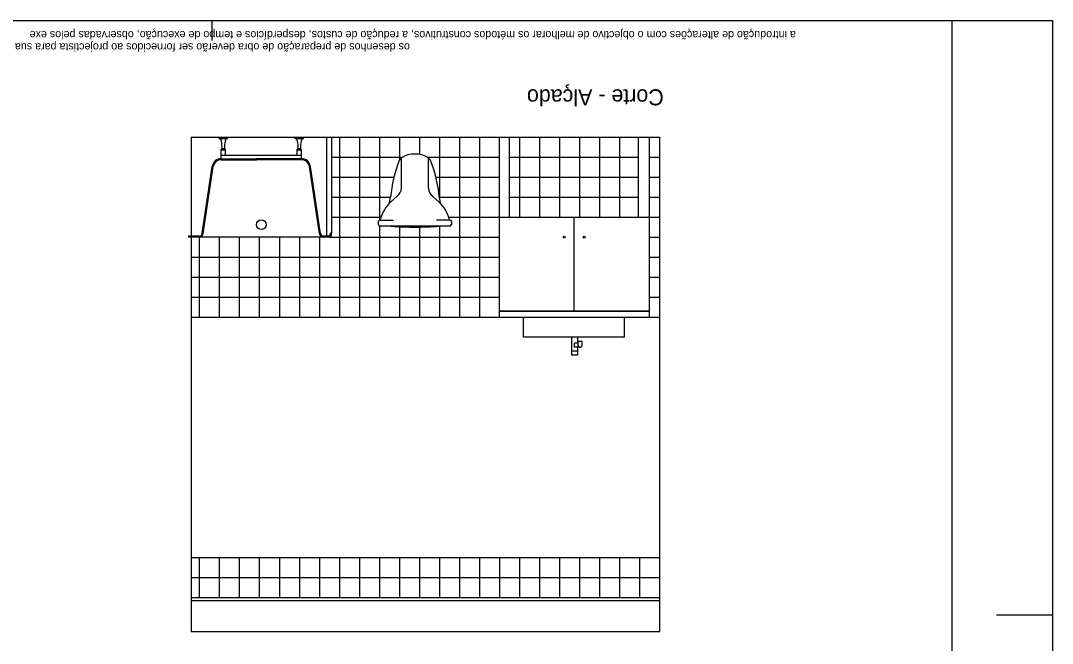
# Model space of a CAD drawing. Extents: x 1289.5 to 1301.1, y -287.4 to -281.5.
# Drawn here: x 1295.93 to 1301.09, y -284.62 to -281.51 of the extents above; entities that cross this region are included whole.
import ezdxf

# ---------------------------------------------------------------- set-up
doc = ezdxf.new("R2010")
doc.units = 0
for name, color, linetype in [('Level 1', 7, 'Continuous'), ('Level 10', 7, 'Continuous'), ('Level 11', 7, 'Continuous'), ('Level 13', 7, 'Continuous'), ('Level 2', 7, 'Continuous'), ('Level 60', 7, 'Continuous'), ('Level 62', 7, 'Continuous')]:
    doc.layers.add(name, color=color, linetype=linetype)

msp = doc.modelspace()

# ---------------------------------------------------------------- linework, layer by layer
at = {"layer": 'Level 1'}
for p, q in [((1296.7865, -282.09), (1296.7865, -284.56)), ((1296.7865, -282.09), (1299.1265, -282.09)), ((1297.4615, -282.09), (1297.4615, -282.585)), ((1297.4865, -282.09), (1297.4865, -282.57)), ((1299.1265, -282.09), (1299.1265, -284.56)), ((1297.4865, -282.57), (1297.4815, -282.57)), ((1297.4815, -282.57), (1297.4815, -282.575)), ((1297.4715, -282.585), (1297.4615, -282.585)), ((1296.7865, -284.39), (1299.1265, -284.39)), ((1296.7865, -284.405), (1299.1265, -284.405)), ((1296.7865, -284.56), (1299.1265, -284.56))]:
    msp.add_line(p, q, dxfattribs=at)
msp.add_arc((1297.4715, -282.575), 0.01, 270, 0, dxfattribs=at)
at = {"layer": 'Level 10'}
for p, q in [((1297.5265, -282.09), (1297.5265, -282.99)), ((1297.6265, -282.09), (1297.6265, -282.99)), ((1297.7265, -282.09), (1297.7265, -282.5048)), ((1297.8265, -282.09), (1297.8265, -282.2058)), ((1297.9265, -282.09), (1297.9265, -282.1767)), ((1298.0265, -282.09), (1298.0265, -282.4011)), ((1298.1265, -282.09), (1298.1265, -282.99)), ((1298.2265, -282.09), (1298.2265, -282.99)), ((1298.4265, -282.09), (1298.4265, -282.49)), ((1298.5265, -282.09), (1298.5265, -282.49)), ((1298.6265, -282.09), (1298.6265, -282.49)), ((1298.7265, -282.09), (1298.7265, -282.49)), ((1298.8265, -282.09), (1298.8265, -282.49)), ((1298.9265, -282.09), (1298.9265, -282.49)), ((1297.4865, -282.19), (1297.8426, -282.19)), ((1297.9659, -282.19), (1298.3245, -282.19)), ((1298.3745, -282.19), (1299.0195, -282.19)), ((1298.4708, -282.19), (1299.0195, -282.19)), ((1299.0745, -282.19), (1299.1265, -282.19)), ((1297.4865, -282.29), (1297.7988, -282.29)), ((1298.009, -282.29), (1298.3245, -282.29)), ((1298.3745, -282.29), (1299.0195, -282.29)), ((1298.4708, -282.29), (1299.0195, -282.29)), ((1299.0745, -282.29), (1299.1265, -282.29)), ((1297.4865, -282.39), (1297.7822, -282.39)), ((1298.0256, -282.39), (1298.3245, -282.39)), ((1298.3745, -282.39), (1299.0195, -282.39)), ((1298.4708, -282.39), (1299.0195, -282.39)), ((1299.0745, -282.39), (1299.1265, -282.39)), ((1297.4865, -282.49), (1297.5765, -282.49)), ((1297.5765, -282.49), (1297.7352, -282.49)), ((1298.0727, -282.49), (1298.3265, -282.49)), ((1299.0745, -282.49), (1299.1265, -282.49)), ((1297.7265, -282.5343), (1297.7265, -282.99)), ((1297.8265, -282.5378), (1297.8265, -282.99)), ((1297.9265, -282.54), (1297.9265, -282.99)), ((1298.0265, -282.5347), (1298.0265, -282.99)), ((1296.8265, -282.59), (1296.8265, -282.99)), ((1296.9265, -282.59), (1296.9265, -282.99)), ((1297.0265, -282.59), (1297.0265, -282.99)), ((1297.1265, -282.59), (1297.1265, -282.99)), ((1297.2265, -282.59), (1297.2265, -282.99)), ((1297.3265, -282.59), (1297.3265, -282.99)), ((1297.4265, -282.59), (1297.4265, -282.99)), ((1297.4765, -282.59), (1297.5765, -282.59)), ((1297.5765, -282.59), (1298.3265, -282.59)), ((1299.0745, -282.59), (1299.1265, -282.59)), ((1296.7865, -282.69), (1297.5765, -282.69)), ((1297.5765, -282.69), (1298.3265, -282.69)), ((1299.0745, -282.69), (1299.1265, -282.69)), ((1296.7865, -282.79), (1297.5765, -282.79)), ((1297.5765, -282.79), (1298.3265, -282.79)), ((1299.0745, -282.79), (1299.1265, -282.79)), ((1296.7865, -282.89), (1297.5765, -282.89)), ((1297.5765, -282.89), (1298.3265, -282.89)), ((1299.0745, -282.89), (1299.1265, -282.89)), ((1296.8265, -284.19), (1296.8265, -284.39)), ((1296.9265, -284.19), (1296.9265, -284.39)), ((1297.0265, -284.19), (1297.0265, -284.39)), ((1297.1265, -284.19), (1297.1265, -284.39)), ((1297.2265, -284.19), (1297.2265, -284.39)), ((1297.3265, -284.19), (1297.3265, -284.39)), ((1297.4265, -284.19), (1297.4265, -284.39)), ((1297.5265, -284.19), (1297.5265, -284.39)), ((1297.6265, -284.19), (1297.6265, -284.39)), ((1297.7265, -284.19), (1297.7265, -284.39)), ((1297.8265, -284.19), (1297.8265, -284.39)), ((1297.9265, -284.19), (1297.9265, -284.39)), ((1298.0265, -284.19), (1298.0265, -284.39)), ((1298.1265, -284.19), (1298.1265, -284.39)), ((1298.2265, -284.19), (1298.2265, -284.39)), ((1298.3265, -284.19), (1298.3265, -284.39)), ((1298.4265, -284.19), (1298.4265, -284.39)), ((1298.5265, -284.19), (1298.5265, -284.39)), ((1298.6265, -284.19), (1298.6265, -284.39)), ((1298.7265, -284.19), (1298.7265, -284.39)), ((1298.8265, -284.19), (1298.8265, -284.39)), ((1298.9265, -284.19), (1298.9265, -284.39)), ((1299.0265, -284.19), (1299.0265, -284.39)), ((1296.7865, -284.29), (1299.1265, -284.29))]:
    msp.add_line(p, q, dxfattribs=at)
at = {"layer": 'Level 11'}
for p, q in [((1296.9258, -282.0899), (1296.9671, -282.0899)), ((1296.9258, -282.0966), (1296.9258, -282.0899)), ((1296.9258, -282.0966), (1296.9671, -282.0966)), ((1296.9671, -282.0966), (1296.9671, -282.0899)), ((1297.306, -282.0899), (1297.3473, -282.0899)), ((1297.306, -282.0966), (1297.306, -282.0899)), ((1297.306, -282.0966), (1297.3473, -282.0966)), ((1297.3473, -282.0966), (1297.3473, -282.0899)), ((1296.9359, -282.1535), (1296.9408, -282.1475)), ((1296.9359, -282.1535), (1296.9569, -282.1535)), ((1296.9359, -282.1799), (1296.9359, -282.1535)), ((1296.9408, -282.1475), (1296.952, -282.1475)), ((1296.9569, -282.1535), (1296.952, -282.1475)), ((1296.9569, -282.1799), (1296.9569, -282.1535)), ((1297.3161, -282.1535), (1297.321, -282.1475)), ((1297.3161, -282.1535), (1297.3371, -282.1535)), ((1297.3161, -282.1799), (1297.3161, -282.1535)), ((1297.321, -282.1475), (1297.3322, -282.1475)), ((1297.3371, -282.1535), (1297.3322, -282.1475)), ((1297.3371, -282.198), (1297.3371, -282.1535)), ((1296.9359, -282.2027), (1296.9359, -282.1799)), ((1296.9359, -282.1799), (1297.3371, -282.1799)), ((1296.9359, -282.198), (1297.1122, -282.198)), ((1296.9359, -282.203), (1297.1122, -282.203)), ((1297.1607, -282.198), (1297.1122, -282.198)), ((1297.1607, -282.203), (1297.1122, -282.203)), ((1297.3371, -282.198), (1297.1607, -282.198)), ((1297.3371, -282.203), (1297.1607, -282.203)), ((1297.8364, -282.3449), (1297.8364, -282.1935)), ((1297.9714, -282.3449), (1297.9714, -282.1935)), ((1296.8415, -282.571), (1296.8914, -282.2364)), ((1296.8464, -282.5717), (1296.8963, -282.2371)), ((1297.4264, -282.5717), (1297.3766, -282.2371)), ((1297.4315, -282.5722), (1297.3816, -282.2364)), ((1297.7779, -282.4189), (1297.7822, -282.3902)), ((1297.7822, -282.4149), (1297.815, -282.3847)), ((1298.0256, -282.4149), (1297.9928, -282.3847)), ((1298.0256, -282.3902), (1298.0299, -282.4189)), ((1297.7214, -282.5269), (1297.7214, -282.5123)), ((1297.7272, -282.5046), (1297.7965, -282.5046)), ((1298.0806, -282.5046), (1298.0113, -282.5046)), ((1298.0864, -282.5123), (1298.0864, -282.5269)), ((1297.4865, -282.57), (1297.4815, -282.57)), ((1297.4815, -282.58), (1297.4815, -282.57)), ((1297.4865, -282.58), (1297.4865, -282.57)), ((1296.8265, -282.585), (1296.7715, -282.585)), ((1296.8265, -282.59), (1296.7715, -282.59)), ((1297.4465, -282.59), (1296.8265, -282.59)), ((1297.4765, -282.59), (1297.4463, -282.59)), ((1297.4765, -282.585), (1297.4464, -282.585)), ((1298.4473, -283.09), (1298.4473, -282.99)), ((1298.9517, -283.09), (1298.9517, -282.99)), ((1298.6868, -283.09), (1298.6868, -283.18)), ((1298.7168, -283.09), (1298.7168, -283.12)), ((1298.6868, -283.14), (1298.6868, -283.18)), ((1298.7168, -283.14), (1298.7168, -283.18)), ((1298.7194, -283.13), (1298.7194, -283.11)), ((1298.7194, -283.11), (1298.7394, -283.11)), ((1298.7394, -283.13), (1298.7394, -283.11)), ((1298.7168, -283.16), (1298.6868, -283.16)), ((1298.7168, -283.18), (1298.6868, -283.18))]:
    msp.add_line(p, q, dxfattribs=at)
msp.add_lwpolyline([(1298.0784, -282.5349), (1297.9014, -282.5349), (1297.7294, -282.5349)], dxfattribs=at)
msp.add_circle((1297.1365, -282.528), 0.0242, dxfattribs=at)
for centre, radius, start, end in [((1296.9193, -282.1138), 0.0182, 10.7191, 69.4894), ((1296.741, -282.1475), 0.1997, 0, 10.7194), ((1297.1517, -282.1475), 0.1997, 169.2807, 180), ((1296.9734, -282.1138), 0.0182, 110.5111, 169.2809), ((1297.2995, -282.1138), 0.0182, 10.7191, 69.4894), ((1297.1213, -282.1475), 0.1997, 0, 10.7194), ((1297.5319, -282.1475), 0.1997, 169.2807, 180), ((1297.3536, -282.1138), 0.0182, 110.5111, 169.2809), ((1296.9359, -282.243), 0.045, 89.9997, 171.5179), ((1296.9359, -282.243), 0.04, 90.0002, 171.5177), ((1297.3371, -282.243), 0.045, 8.4597, 90), ((1297.3371, -282.243), 0.04, 8.46, 90.0002), ((1298.4059, -282.4424), 0.6258, 157.8783, 175.2216), ((1297.8569, -282.2201), 0.0336, 127.3751, 156.3615), ((1297.9039, -282.306), 0.1312, 59.0523, 120.9477), ((1297.951, -282.2201), 0.0336, 23.6385, 52.6249), ((1297.402, -282.4424), 0.6258, 4.7784, 22.1217), ((1297.7849, -282.3428), 0.0516, 305.6694, 357.6894), ((1298.023, -282.3428), 0.0516, 182.3106, 234.3306), ((1297.8959, -282.5383), 0.1678, 132.6634, 166.3829), ((1297.9119, -282.5383), 0.1678, 13.6171, 47.3366), ((1297.7295, -282.5122), 0.008, 106.0135, 180), ((1297.7295, -282.5269), 0.008, 180, 270), ((1297.7251, -282.4969), 0.008, 286.0135, 346.3829), ((1298.0828, -282.4969), 0.008, 193.6171, 253.9865), ((1298.0784, -282.5269), 0.008, 270, 0), ((1298.0784, -282.5122), 0.008, 0, 73.9865), ((1296.8265, -282.57), 0.015, 269.9995, 355.2362), ((1296.8265, -282.57), 0.02, 269.9995, 355.2362), ((1297.4463, -282.57), 0.02, 184.7628, 270.0004), ((1297.4464, -282.57), 0.015, 188.4592, 269.9992), ((1297.4765, -282.58), 0.005, 269.9998, 359.9959), ((1297.4765, -282.58), 0.01, 269.9988, 0.0008), ((1297.9105, -280.9802), 1.5598, 265.3355, 269.8515), ((1297.8964, -280.9644), 1.5757, 270.3677, 274.6531), ((1298.7294, -283.13), 0.01, 180, 0)]:
    msp.add_arc(centre, radius, start, end, dxfattribs=at)
at = {"layer": 'Level 13'}
for p, q in [((1298.3245, -282.09), (1298.3245, -282.99)), ((1298.3745, -282.09), (1298.3745, -282.49)), ((1299.0195, -282.09), (1299.0195, -282.49)), ((1299.0745, -282.09), (1299.0745, -282.99)), ((1298.3245, -282.49), (1299.0745, -282.49)), ((1298.6995, -282.958), (1298.6995, -282.49)), ((1298.3245, -282.958), (1299.0745, -282.958)), ((1298.3245, -282.96), (1299.0745, -282.96)), ((1298.3245, -282.99), (1299.0745, -282.99)), ((1298.9517, -283.09), (1298.4473, -283.09))]:
    msp.add_line(p, q, dxfattribs=at)
for centre in [(1298.6495, -282.59), (1298.7495, -282.59)]:
    msp.add_circle(centre, 0.005, dxfattribs=at)
at = {"layer": 'Level 2'}
for p, q in [((1296.7865, -282.99), (1297.5765, -282.99)), ((1297.5765, -282.99), (1298.3265, -282.99)), ((1299.0745, -282.99), (1299.1265, -282.99)), ((1298.7018, -283.14), (1298.7018, -283.12)), ((1298.7194, -283.12), (1298.7018, -283.12)), ((1298.7294, -283.14), (1298.7018, -283.14)), ((1296.7865, -284.19), (1299.1265, -284.19))]:
    msp.add_line(p, q, dxfattribs=at)
at = {"layer": 'Level 62'}
for p, q in [((1296.8905, -281.6083), (1296.8905, -281.5083)), ((1300.5901, -287.4483), (1300.5901, -281.5083)), ((1301.0901, -284.4783), (1300.8101, -284.4783))]:
    msp.add_line(p, q, dxfattribs=at)
msp.add_lwpolyline([(1301.0901, -281.5083), (1301.0901, -287.4483), (1289.4905, -287.4483), (1289.4905, -281.5083)], close=True, dxfattribs=at)

# ---------------------------------------------------------------- texts
at = {"layer": 'Level 60'}
msp.add_text('Corte - Alçado', height=0.08, rotation=180, dxfattribs=at).set_placement((1299.1478, -281.8514))
at = {"layer": 'Level 62'}
for s, height, p in [('a introdução de alterações com o objectivo de melhorar os métodos construtivos, a redução de custos, desperdícios e tempo de execução, observadas pelos exe', 0.0399996, (1299.8081, -281.5603)), ('os desenhos de preparação de obra deverão ser fornecidos ao projectista para sua aprovação -', 0.04, (1297.8791, -281.6213))]:
    msp.add_text(s, height=height, rotation=180, dxfattribs=at).set_placement(p)

doc.saveas('drawing.dxf')
